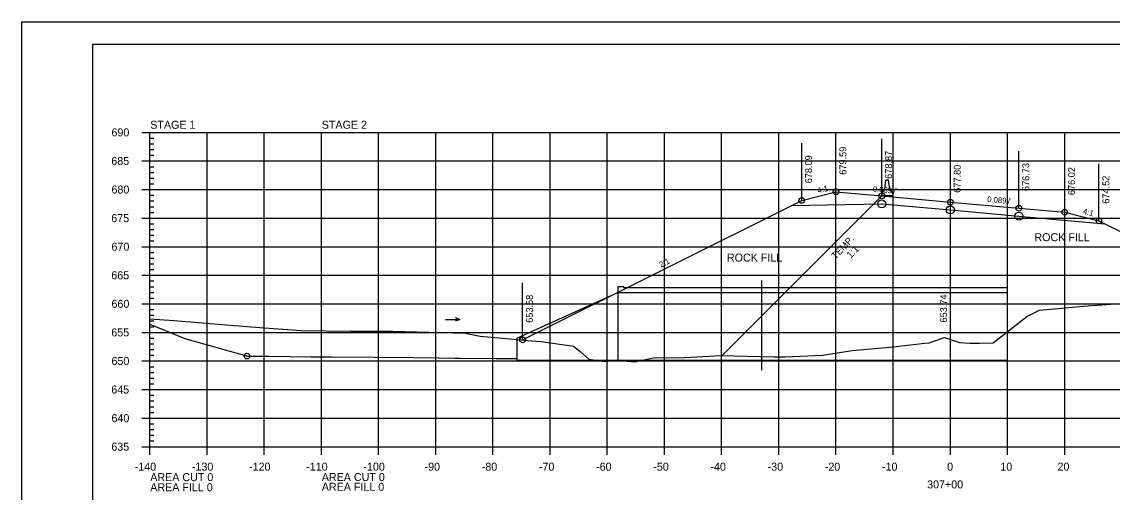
# Model space of a CAD drawing. Extents: x 1370515 to 1370849, y 383299 to 386073.
# Drawn here: x 1370515.4 to 1370706.1, y 384283.8 to 384366.1 of the extents above; entities that cross this region are included whole.
import ezdxf

# ---------------------------------------------------------------- set-up
doc = ezdxf.new("R2010")
doc.units = 0
for name, color, linetype in [('R_Alt Surface', 7, 'Continuous'), ('R_Axis', 7, 'Continuous'), ('R_Axis Annot', 7, 'Continuous'), ('R_Border', 7, 'Continuous'), ('R_Detour', 7, 'Continuous'), ('R_Exist Surface', 7, 'Continuous'), ('R_Fin Surface', 7, 'Continuous'), ('R_Grid', 7, 'Continuous'), ('R_No Plot', 7, 'Continuous'), ('R_Water', 7, 'Continuous'), ('R_Water Annot', 7, 'Continuous'), ('R_Xsect Elev', 7, 'Continuous'), ('R_Xsect Slope', 7, 'Continuous')]:
    doc.layers.add(name, color=color, linetype=linetype)

msp = doc.modelspace()

# ---------------------------------------------------------------- linework, layer by layer
at = {"layer": 'R_Alt Surface'}
msp.add_lwpolyline([(1370649.98, 384333.94), (1370665.8, 384334.25), (1370677.8, 384333.19), (1370689.8, 384332.11), (1370704.83, 384330.76)], dxfattribs=at)
at = {"layer": 'R_Axis'}
for p, q in [((1370536.4, 384346.76), (1370539.2, 384346.76)), ((1370537.8, 384291.76), (1370537.8, 384346.76)), ((1370537.8, 384345.76), (1370538.5, 384345.76)), ((1370537.8, 384344.76), (1370538.5, 384344.76)), ((1370537.8, 384343.76), (1370538.5, 384343.76)), ((1370537.8, 384342.76), (1370538.5, 384342.76)), ((1370536.4, 384341.76), (1370539.2, 384341.76)), ((1370537.8, 384340.76), (1370538.5, 384340.76)), ((1370537.8, 384339.76), (1370538.5, 384339.76)), ((1370537.8, 384338.76), (1370538.5, 384338.76)), ((1370537.8, 384337.76), (1370538.5, 384337.76)), ((1370536.4, 384336.76), (1370539.2, 384336.76)), ((1370537.8, 384335.76), (1370538.5, 384335.76)), ((1370537.8, 384334.76), (1370538.5, 384334.76)), ((1370537.8, 384333.76), (1370538.5, 384333.76)), ((1370536.4, 384331.76), (1370539.2, 384331.76)), ((1370537.8, 384332.76), (1370538.5, 384332.76)), ((1370537.8, 384330.76), (1370538.5, 384330.76)), ((1370537.8, 384329.76), (1370538.5, 384329.76)), ((1370537.8, 384328.76), (1370538.5, 384328.76)), ((1370537.8, 384327.76), (1370538.5, 384327.76)), ((1370536.4, 384326.76), (1370539.2, 384326.76)), ((1370537.8, 384325.76), (1370538.5, 384325.76)), ((1370537.8, 384324.76), (1370538.5, 384324.76)), ((1370537.8, 384323.76), (1370538.5, 384323.76)), ((1370536.4, 384321.76), (1370539.2, 384321.76)), ((1370537.8, 384322.76), (1370538.5, 384322.76)), ((1370537.8, 384320.76), (1370538.5, 384320.76)), ((1370537.8, 384319.76), (1370538.5, 384319.76)), ((1370537.8, 384318.76), (1370538.5, 384318.76)), ((1370537.8, 384317.76), (1370538.5, 384317.76)), ((1370536.4, 384316.76), (1370539.2, 384316.76)), ((1370537.8, 384315.76), (1370538.5, 384315.76)), ((1370537.8, 384314.76), (1370538.5, 384314.76)), ((1370537.8, 384313.76), (1370538.5, 384313.76)), ((1370537.8, 384312.76), (1370538.5, 384312.76)), ((1370536.4, 384311.76), (1370539.2, 384311.76)), ((1370537.8, 384310.76), (1370538.5, 384310.76)), ((1370537.8, 384309.76), (1370538.5, 384309.76)), ((1370537.8, 384308.76), (1370538.5, 384308.76)), ((1370536.4, 384306.76), (1370539.2, 384306.76)), ((1370537.8, 384307.76), (1370538.5, 384307.76)), ((1370537.8, 384305.76), (1370538.5, 384305.76)), ((1370537.8, 384304.76), (1370538.5, 384304.76)), ((1370537.8, 384303.76), (1370538.5, 384303.76)), ((1370537.8, 384302.76), (1370538.5, 384302.76)), ((1370536.4, 384301.76), (1370539.2, 384301.76)), ((1370537.8, 384300.76), (1370538.5, 384300.76)), ((1370537.8, 384299.76), (1370538.5, 384299.76)), ((1370537.8, 384298.76), (1370538.5, 384298.76)), ((1370536.4, 384296.76), (1370539.2, 384296.76)), ((1370537.8, 384297.76), (1370538.5, 384297.76)), ((1370537.8, 384295.76), (1370538.5, 384295.76)), ((1370537.8, 384294.76), (1370538.5, 384294.76)), ((1370537.8, 384293.76), (1370538.5, 384293.76)), ((1370537.8, 384290.36), (1370537.8, 384293.16)), ((1370547.8, 384290.36), (1370547.8, 384293.16)), ((1370557.8, 384290.36), (1370557.8, 384293.16)), ((1370567.8, 384290.36), (1370567.8, 384293.16)), ((1370577.8, 384290.36), (1370577.8, 384293.16)), ((1370587.8, 384290.36), (1370587.8, 384293.16)), ((1370597.8, 384290.36), (1370597.8, 384293.16)), ((1370607.8, 384290.36), (1370607.8, 384293.16)), ((1370617.8, 384290.36), (1370617.8, 384293.16)), ((1370627.8, 384290.36), (1370627.8, 384293.16)), ((1370637.8, 384290.36), (1370637.8, 384293.16)), ((1370647.8, 384290.36), (1370647.8, 384293.16)), ((1370657.8, 384290.36), (1370657.8, 384293.16)), ((1370667.8, 384290.36), (1370667.8, 384293.16)), ((1370677.8, 384290.36), (1370677.8, 384293.16)), ((1370687.8, 384290.36), (1370687.8, 384293.16)), ((1370697.8, 384290.36), (1370697.8, 384293.16)), ((1370536.4, 384291.76), (1370539.2, 384291.76)), ((1370537.8, 384292.76), (1370538.5, 384292.76)), ((1370537.8, 384291.76), (1370817.8, 384291.76))]:
    msp.add_line(p, q, dxfattribs=at)
at = {"layer": 'R_Border'}
for p, q in [((1370527.8, 384362.22), (1370843.98, 384362.22)), ((1370527.8, 384156.76), (1370527.8, 384362.22)), ((1370680.32, 384361.96), (1370680.32, 384361.96)), ((1370680.32, 384361.96), (1370680.32, 384361.96))]:
    msp.add_line(p, q, dxfattribs=at)
at = {"layer": 'R_Detour'}
for p, q in [((1370665.8, 384335.97), (1370666.36, 384336.81)), ((1370666.36, 384336.81), (1370666.5, 384338.4)), ((1370666.75, 384338.4), (1370666.5, 384338.4)), ((1370667, 384338.41), (1370666.75, 384338.4)), ((1370667.19, 384336.83), (1370667, 384338.41)), ((1370667.8, 384336.01), (1370667.19, 384336.83)), ((1370665.8, 384335.63), (1370637.87, 384307.71)), ((1370665.8, 384335.63), (1370665.8, 384335.97)), ((1370667.8, 384335.67), (1370665.8, 384335.63)), ((1370667.8, 384335.67), (1370667.8, 384336.01)), ((1370644.82, 384305.15), (1370644.82, 384320.87))]:
    msp.add_line(p, q, dxfattribs=at)
at = {"layer": 'R_Exist Surface'}
msp.add_lwpolyline([(1370537.8, 384314.16), (1370541.98, 384313.83), (1370555.45, 384312.72), (1370564.25, 384312.08), (1370572.86, 384311.98), (1370580.31, 384311.97), (1370592.94, 384311.62), (1370595.55, 384311.09), (1370602.65, 384310.47), (1370603.85, 384310.37), (1370605.35, 384310.23), (1370606.23, 384310.16), (1370611.86, 384309.35), (1370613, 384308.47), (1370614.58, 384307.08), (1370617.39, 384306.66), (1370619.27, 384306.93), (1370622.64, 384306.62), (1370625.83, 384307.29), (1370631.3, 384307.34), (1370637.71, 384307.71), (1370644.58, 384307.56), (1370646.97, 384307.5), (1370648.91, 384307.51), (1370655.47, 384307.75), (1370658.01, 384308.18), (1370660.7, 384308.6), (1370667.8, 384309.24), (1370673.31, 384309.85), (1370674.07, 384309.92), (1370676.75, 384310.84), (1370679.4, 384309.98), (1370681.23, 384309.86), (1370682.89, 384309.85), (1370685.29, 384309.91), (1370691.15, 384314.57), (1370693.4, 384315.65), (1370701.08, 384316.36), (1370707.48, 384316.79)], dxfattribs=at)
at = {"layer": 'R_Fin Surface'}
for points in [[(1370602.99, 384310.44), (1370651.8, 384334.85), (1370657.8, 384336.35), (1370665.8, 384335.63), (1370677.8, 384334.56), (1370689.8, 384333.49), (1370697.8, 384332.78), (1370703.8, 384331.28), (1370708.83, 384328.76), (1370730.24, 384318.06)], [(1370537.8, 384313.19), (1370543.93, 384310.72), (1370554.67, 384307.65), (1370554.73, 384307.63), (1370554.78, 384307.61), (1370557.89, 384307.59), (1370558.64, 384307.58), (1370565.93, 384307.51), (1370569.65, 384307.48), (1370577.12, 384307.41), (1370583.87, 384307.35), (1370588.31, 384307.31), (1370591.12, 384307.28), (1370592.14, 384307.27), (1370598.33, 384307.22), (1370599.5, 384307.21), (1370601.96, 384307.18)]]:
    msp.add_lwpolyline(points, dxfattribs=at)
at = {"layer": 'R_Grid'}
for p, q in [((1370537.8, 384346.76), (1370817.8, 384346.76)), ((1370537.8, 384291.76), (1370537.8, 384346.76)), ((1370547.8, 384291.76), (1370547.8, 384346.76)), ((1370557.8, 384291.76), (1370557.8, 384346.76)), ((1370567.8, 384291.76), (1370567.8, 384346.76)), ((1370577.8, 384291.76), (1370577.8, 384346.76)), ((1370587.8, 384291.76), (1370587.8, 384346.76)), ((1370597.8, 384291.76), (1370597.8, 384346.76)), ((1370607.8, 384291.76), (1370607.8, 384346.76)), ((1370617.8, 384291.76), (1370617.8, 384346.76)), ((1370627.8, 384291.76), (1370627.8, 384346.76)), ((1370637.8, 384291.76), (1370637.8, 384346.76)), ((1370647.8, 384291.76), (1370647.8, 384346.76)), ((1370657.8, 384291.76), (1370657.8, 384346.76)), ((1370667.8, 384291.76), (1370667.8, 384346.76)), ((1370677.8, 384291.76), (1370677.8, 384346.76)), ((1370687.8, 384291.76), (1370687.8, 384346.76)), ((1370697.8, 384291.76), (1370697.8, 384346.76)), ((1370537.8, 384341.76), (1370817.8, 384341.76)), ((1370537.8, 384336.76), (1370817.8, 384336.76)), ((1370537.8, 384331.76), (1370817.8, 384331.76)), ((1370537.8, 384326.76), (1370817.8, 384326.76)), ((1370537.8, 384321.76), (1370817.8, 384321.76)), ((1370537.8, 384316.76), (1370817.8, 384316.76)), ((1370537.8, 384311.76), (1370817.8, 384311.76)), ((1370537.8, 384306.76), (1370817.8, 384306.76)), ((1370537.8, 384301.76), (1370817.8, 384301.76)), ((1370537.8, 384296.76), (1370817.8, 384296.76)), ((1370537.8, 384291.76), (1370817.8, 384291.76))]:
    msp.add_line(p, q, dxfattribs=at)
at = {"layer": 'R_No Plot'}
msp.add_line((1370515.4, 384366.12), (1370848.73, 384366.12), dxfattribs=at)
for points in [[(1370515.39, 384366.12), (1370848.73, 384366.12), (1370848.73, 384152.78), (1370515.39, 384152.78)], [(1370761.72, 384362.22), (1370761.72, 384352.34), (1370797.45, 384352.34), (1370797.45, 384349.42), (1370820.65, 384349.42), (1370820.65, 384326.21), (1370843.98, 384326.21), (1370843.98, 384156.76), (1370527.8, 384156.76), (1370527.8, 384362.22)]]:
    msp.add_lwpolyline(points, close=True, dxfattribs=at)
for centre, radius in [((1370657.8, 384336.35), 0.5), ((1370651.8, 384334.85), 0.5), ((1370651.8, 384334.85), 0.5), ((1370665.8, 384334.25), 0.7), ((1370665.8, 384335.63), 0.5), ((1370677.8, 384334.56), 0.5), ((1370677.8, 384333.19), 0.7), ((1370677.8, 384333.19), 0.7), ((1370689.8, 384333.49), 0.5), ((1370697.8, 384332.78), 0.5), ((1370689.8, 384332.11), 0.7), ((1370703.8, 384331.28), 0.5), ((1370703.8, 384331.28), 0.5), ((1370602.99, 384310.44), 0.5), ((1370554.78, 384307.61), 0.5), ((1370554.78, 384307.61), 0.5)]:
    msp.add_circle(centre, radius, dxfattribs=at)
at = {"layer": 'R_Water'}
for p, q in [((1370619.65, 384319.78), (1370620.65, 384319.78)), ((1370619.65, 384319.78), (1370619.65, 384318.75)), ((1370620.65, 384319.78), (1370620.65, 384319.63)), ((1370620.65, 384319.63), (1370687.82, 384319.63)), ((1370601.98, 384310.75), (1370619.65, 384318.75)), ((1370619.65, 384318.75), (1370687.82, 384318.75)), ((1370619.65, 384318.75), (1370619.65, 384306.88)), ((1370601.98, 384310.75), (1370601.98, 384306.88)), ((1370601.98, 384306.88), (1370687.82, 384306.88))]:
    msp.add_line(p, q, dxfattribs=at)
at = {"layer": 'R_Water Annot'}
for p, q in [((1370589.49, 384314.03), (1370592.01, 384314.03)), ((1370592.01, 384314.03), (1370591.24, 384314.31)), ((1370592.01, 384314.03), (1370591.24, 384313.75))]:
    msp.add_line(p, q, dxfattribs=at)
at = {"layer": 'R_Xsect Elev'}
for p, q in [((1370657.8, 384336.35), (1370657.8, 384346.35)), ((1370651.8, 384334.85), (1370651.8, 384344.85)), ((1370665.8, 384335.63), (1370665.8, 384345.63)), ((1370677.8, 384333.19), (1370677.8, 384343.19)), ((1370689.8, 384333.49), (1370689.8, 384343.49)), ((1370697.8, 384332.78), (1370697.8, 384342.78)), ((1370703.8, 384331.28), (1370703.8, 384341.28)), ((1370602.99, 384310.44), (1370602.99, 384320.44)), ((1370677.82, 384310.49), (1370677.82, 384320.49))]:
    msp.add_line(p, q, dxfattribs=at)

# ---------------------------------------------------------------- texts
at = {"layer": 'R_Axis'}
msp.add_text('-', height=0.0001, dxfattribs=at).set_placement((1370537.8, 384291.76))
at = {"layer": 'R_Axis Annot'}
for s, p in [('STAGE 1', (1370537.86, 384347.4)), ('STAGE 2', (1370567.86, 384347.4)), ('690', (1370531.08, 384346.06)), ('685', (1370531.05, 384341.06)), ('680', (1370531.08, 384336.06)), ('675', (1370531.05, 384331.06)), ('670', (1370531.08, 384326.06)), ('ROCK FILL', (1370692.51, 384327.72)), ('ROCK FILL', (1370638.72, 384324.15)), ('665', (1370531.05, 384321.06)), ('660', (1370531.08, 384316.06)), ('655', (1370531.05, 384311.06)), ('650', (1370531.08, 384306.06)), ('645', (1370531.05, 384301.06)), ('640', (1370531.08, 384296.06)), ('635', (1370531.05, 384291.06)), ('-140', (1370535.14, 384287.56)), ('-130', (1370545.14, 384287.56)), ('-120', (1370555.14, 384287.56)), ('-110', (1370565.14, 384287.56)), ('-100', (1370575.14, 384287.56)), ('-90', (1370585.84, 384287.56)), ('-80', (1370595.84, 384287.56)), ('-70', (1370605.84, 384287.56)), ('-60', (1370615.84, 384287.56)), ('-50', (1370625.84, 384287.56)), ('-40', (1370635.84, 384287.56)), ('-30', (1370645.84, 384287.56)), ('-20', (1370655.84, 384287.56)), ('-10', (1370665.84, 384287.56)), ('0', (1370677.24, 384287.56)), ('10', (1370686.54, 384287.56)), ('20', (1370696.54, 384287.56)), ('AREA CUT 0', (1370537.86, 384285.73)), ('AREA FILL 0', (1370537.86, 384283.96)), ('AREA CUT 0', (1370567.86, 384285.75)), ('AREA FILL 0', (1370567.86, 384284.04)), ('307+00', (1370673.74, 384284.46))]:
    msp.add_text(s, height=1.4, dxfattribs=at).set_placement(p)
at = {"layer": 'R_Detour'}
for s, p in [('TEMP.', (1370657.74, 384324.47)), ('1:1', (1370660.38, 384324.64))]:
    msp.add_text(s, height=1.2, rotation=46.5651, dxfattribs=at).set_placement(p)
at = {"layer": 'R_No Plot'}
for p in [(1370693.36, 384315.6), (1370564.21, 384312.03), (1370595.5, 384311.04), (1370605.31, 384310.18), (1370676.7, 384310.79), (1370611.82, 384309.3), (1370660.66, 384308.55), (1370673.27, 384309.8), (1370681.18, 384309.81), (1370685.25, 384309.86), (1370614.54, 384307.03), (1370622.6, 384306.57), (1370637.67, 384307.66), (1370646.93, 384307.45), (1370655.43, 384307.7)]:
    msp.add_text('+', height=0.1, dxfattribs=at).set_placement(p)
at = {"layer": 'R_Xsect Elev'}
for s, p in [('678.09', (1370653.6, 384337.85)), ('679.59', (1370659.6, 384339.35)), ('678.87', (1370667.6, 384338.63)), ('677.80', (1370679.6, 384336.19)), ('676.73', (1370691.6, 384336.49)), ('676.02', (1370699.6, 384335.78)), ('674.52', (1370705.6, 384334.28)), ('653.68', (1370604.79, 384313.44)), ('653.74', (1370677.22, 384313.49))]:
    msp.add_text(s, height=1.2, rotation=90, dxfattribs=at).set_placement(p)
at = {"layer": 'R_Xsect Slope'}
for s, rotation, p in [('4:1', 14.0362, (1370654.68, 384336.08)), ("0.089'/'", 354.8995, (1370664.22, 384336.38)), ("0.089'/'", 354.8995, (1370684.22, 384334.59)), ('4:1', 345.9638, (1370700.92, 384332.51)), ('2:1', 26.5651, (1370627.17, 384323.09))]:
    msp.add_text(s, height=1, rotation=rotation, dxfattribs=at).set_placement(p)

doc.saveas('drawing.dxf')
